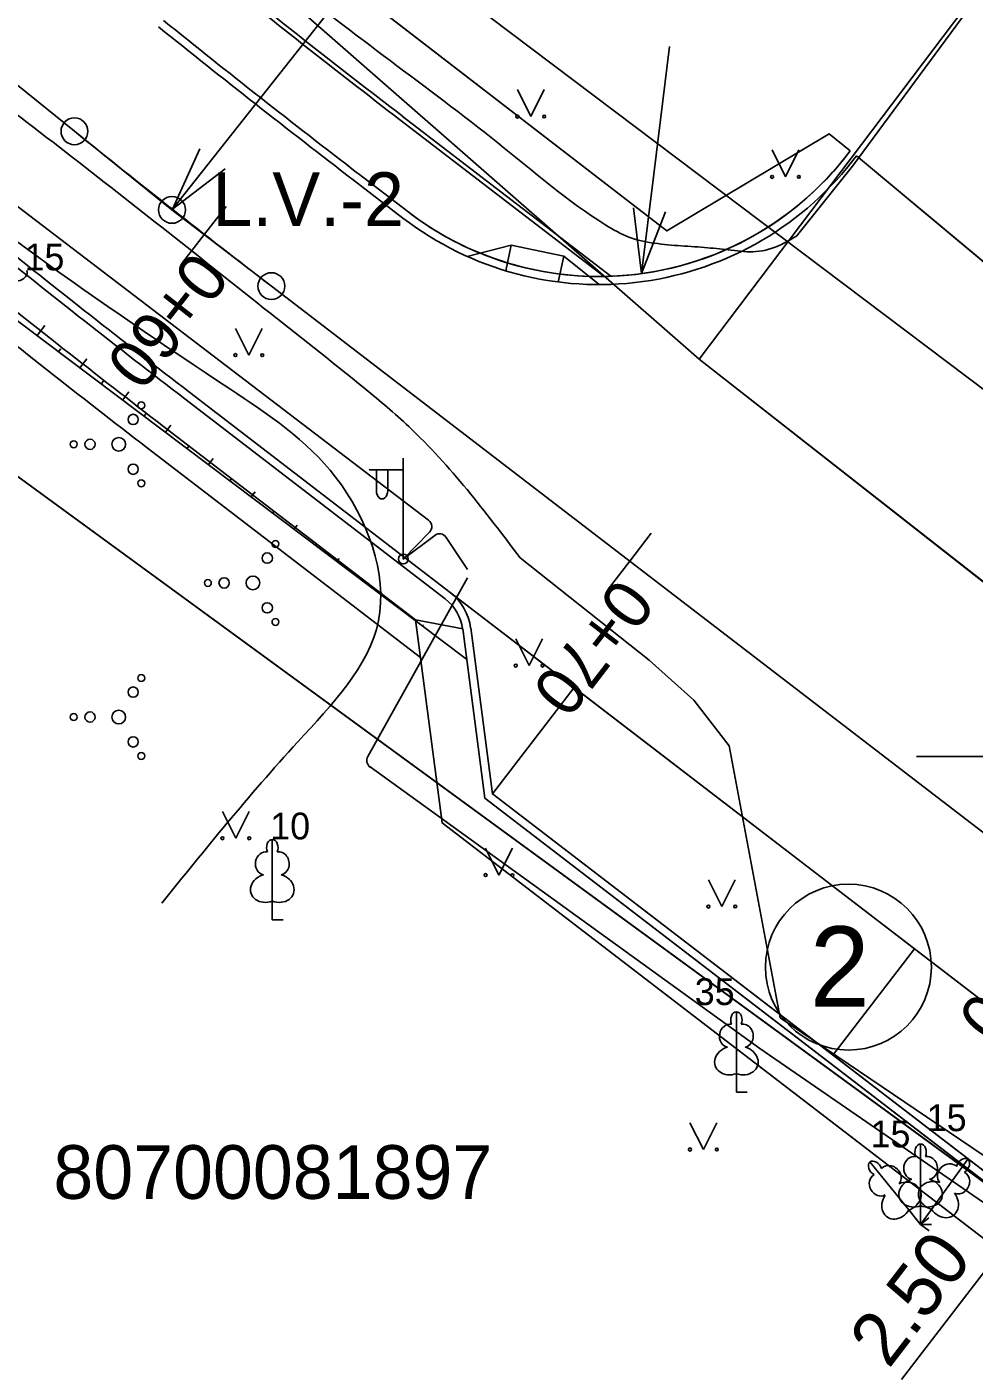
# Model space of a CAD drawing. Extents: x 514086 to 514457, y 297399 to 297567.
# Drawn here: x 514181.92 to 514199.57, y 297438.52 to 297463.61 of the extents above; entities that cross this region are included whole.
import ezdxf

# ---------------------------------------------------------------- set-up
doc = ezdxf.new("R2010")
doc.units = 0
for name, color, linetype in [('AA_Apzimejumi', 7, 'Continuous'), ('AA_Brauktuve', 7, 'Continuous'), ('AA_cela_mala', 7, 'Continuous'), ('AA_Ielas_ass', 7, 'Continuous'), ('AA_Ietve', 7, 'Continuous'), ('AA_izmeri', 7, 'Continuous'), ('AA_noejas', 7, 'Continuous'), ('AA_nogaze', 7, 'Continuous'), ('AA_Nomale', 7, 'Continuous'), ('AA_Stavvietas', 7, 'Continuous'), ('AA_Zale', 7, 'Continuous'), ('Level 1', 7, 'Continuous'), ('Level 21', 7, 'Continuous'), ('Level 23', 7, 'Continuous'), ('Level 29', 7, 'Continuous'), ('Level 30', 7, 'Continuous'), ('Level 37', 7, 'Continuous'), ('Level 44', 7, 'Continuous'), ('Level 45', 7, 'Continuous'), ('Level 46', 7, 'Continuous'), ('Level 59', 7, 'Continuous'), ('Level 8', 7, 'Continuous')]:
    doc.layers.add(name, color=color, linetype=linetype)

msp = doc.modelspace()

# ---------------------------------------------------------------- linework, layer by layer
at = {"layer": 'AA_Apzimejumi'}
msp.add_circle((514197.229, 297446.074), 1.546, dxfattribs=at)
at = {"layer": 'AA_Brauktuve'}
for points in [[(514201.37, 297457.873), (514197.38, 297461.203)], [(514188.925, 297460.043), (514187.996, 297460.756)], [(514184.951, 297456.79), (514189.806, 297453.062), (514189.806, 297453.062), (514192.117, 297451.287), (514198.462, 297446.415), (514204.811, 297441.539), (514204.858, 297441.502), (514204.858, 297441.502)], [(514204.858, 297441.502), (514204.858, 297441.502), (514204.811, 297441.539), (514198.462, 297446.415), (514192.117, 297451.287), (514189.806, 297453.062)], [(514190.188, 297452.399), (514190.594, 297449.304), (514203.335, 297439.52)]]:
    msp.add_lwpolyline(points, dxfattribs=at)
for centre, radius, start, end in [((514308.288, 297617.396), 197.5, 231.13942, 232.4775), ((514192.579, 297464.802), 6, 232.4775, 323.1507), ((514308.288, 297617.396), 202.5, 231.13942, 232.4775), ((514189.196, 297452.269), 1, 7.4775, 52.4769)]:
    msp.add_arc(centre, radius, start, end, dxfattribs=at)
at = {"layer": 'AA_cela_mala'}
for p, q in [((514192.676, 297458.952), (514188.861, 297461.882)), ((514188.91, 297461.945), (514192.803, 297458.956)), ((514197.38, 297461.203), (514201.37, 297457.873)), ((514189.016, 297460.162), (514188.088, 297460.875)), ((514187.996, 297460.756), (514188.925, 297460.043)), ((514184.951, 297456.79), (514189.806, 297453.062)), ((514184.86, 297456.671), (514189.714, 297452.943)), ((514189.806, 297453.062), (514204.858, 297441.502)), ((514190.039, 297452.38), (514190.454, 297449.223)), ((514190.594, 297449.304), (514190.188, 297452.399)), ((514190.594, 297449.304), (514203.335, 297439.52)), ((514190.454, 297449.223), (514203.244, 297439.401))]:
    msp.add_line(p, q, dxfattribs=at)
for centre, radius, start, end in [((514308.288, 297617.396), 196.08, 231.13942, 232.4775), ((514308.288, 297617.396), 196, 231.13942, 232.4775), ((514308.288, 297617.396), 197.5, 231.13942, 232.4775), ((514308.288, 297617.396), 197.35, 231.13942, 232.4775), ((514192.579, 297464.802), 5.85, 270.0269, 323.1507), ((514192.579, 297464.802), 6, 232.4775, 323.1507), ((514192.579, 297464.802), 5.85, 232.4775, 245.8215), ((514308.288, 297617.396), 202.65, 231.13942, 232.4775), ((514308.288, 297617.396), 202.5, 231.13942, 232.4775), ((514192.579, 297464.802), 5.85, 245.8215, 270.0269), ((514189.196, 297452.269), 1, 7.4775, 52.4775), ((514189.196, 297452.269), 0.85, 7.4766, 52.4772)]:
    msp.add_arc(centre, radius, start, end, dxfattribs=at)
at = {"layer": 'AA_Ielas_ass'}
for p, q in [((514159.568, 297480.383), (514182.803, 297461.661)), ((514182.803, 297461.661), (514184.621, 297460.195)), ((514184.621, 297460.195), (514186.474, 297458.773)), ((514185.226, 297459.74), (514185.63, 297460.259)), ((514185.226, 297459.74), (514184.821, 297459.222)), ((514186.474, 297458.773), (514206.381, 297443.485)), ((514193.152, 297453.644), (514193.553, 297454.166)), ((514193.152, 297453.644), (514192.752, 297453.122))]:
    msp.add_line(p, q, dxfattribs=at)
for centre in [(514182.803, 297461.661), (514184.621, 297460.195), (514186.474, 297458.773)]:
    msp.add_circle(centre, 0.25, dxfattribs=at)
msp.add_arc((514308.288, 297617.396), 200, 231.13942, 232.4775, dxfattribs=at)
at = {"layer": 'AA_Ietve'}
for points in [[(514192.676, 297458.952), (514188.861, 297461.882)], [(514188.088, 297460.875), (514189.016, 297460.162)]]:
    msp.add_lwpolyline(points, dxfattribs=at)
for centre, radius, start, end in [((514308.288, 297617.396), 196.08, 231.13942, 232.4775), ((514308.288, 297617.396), 197.35, 231.13942, 232.4775), ((514192.579, 297464.802), 5.85, 232.4775, 270.9501)]:
    msp.add_arc(centre, radius, start, end, dxfattribs=at)
at = {"layer": 'AA_izmeri'}
for p, q in [((514184.63, 297460.206), (514187.714, 297464.105)), ((514193.894, 297463.24), (514193.602, 297460.858)), ((514193.374, 297459.006), (514193.602, 297460.858)), ((514198.217, 297438.384), (514200.665, 297441.571))]:
    msp.add_line(p, q, dxfattribs=at)
for points in [[(514185.61, 297460.961), (514184.63, 297460.206), (514185.139, 297461.333)], [(514193.818, 297460.16), (514193.374, 297459.006), (514193.223, 297460.233)]]:
    msp.add_lwpolyline(points, dxfattribs=at)
at = {"layer": 'AA_noejas'}
for p, q in [((514190.944, 297459.54), (514190.122, 297459.328)), ((514190.841, 297459.059), (514190.944, 297459.54)), ((514190.944, 297459.54), (514191.922, 297459.33)), ((514191.819, 297458.85), (514191.922, 297459.33)), ((514191.922, 297459.33), (514192.582, 297458.802))]:
    msp.add_line(p, q, dxfattribs=at)
at = {"layer": 'AA_nogaze'}
for p, q in [((514182.107, 297457.854), (514182.248, 297458.041)), ((514182.506, 297457.553), (514182.546, 297457.606)), ((514182.905, 297457.252), (514183.032, 297457.42)), ((514183.304, 297456.951), (514183.34, 297456.999)), ((514183.704, 297456.65), (514183.817, 297456.8)), ((514184.103, 297456.349), (514184.135, 297456.391)), ((514184.502, 297456.048), (514184.601, 297456.179)), ((514184.901, 297455.747), (514184.929, 297455.783)), ((514185.301, 297455.446), (514185.386, 297455.558)), ((514185.7, 297455.145), (514185.723, 297455.176)), ((514186.099, 297454.844), (514186.17, 297454.938)), ((514186.498, 297454.543), (514186.517, 297454.568)), ((514186.898, 297454.242), (514186.954, 297454.317)), ((514187.297, 297453.941), (514187.312, 297453.96)), ((514187.696, 297453.64), (514187.739, 297453.696)), ((514188.095, 297453.339), (514188.106, 297453.353)), ((514188.495, 297453.038), (514188.523, 297453.075)), ((514188.894, 297452.737), (514188.9, 297452.745)), ((514189.293, 297452.436), (514189.307, 297452.455)), ((514189.692, 297452.135), (514189.694, 297452.137)), ((514190.092, 297451.834), (514190.092, 297451.834))]:
    msp.add_line(p, q, dxfattribs=at)
msp.add_lwpolyline([(514139.381, 297492.411), (514153.448, 297479.653), (514157.356, 297476.515), (514190.113, 297451.817)], dxfattribs=at)
at = {"layer": 'AA_Nomale'}
for points in [[(514189.714, 297452.943), (514184.86, 297456.671)], [(514184.464, 297456.156), (514189.16, 297452.549), (514190.039, 297452.38)]]:
    msp.add_lwpolyline(points, dxfattribs=at)
for centre, radius, start, end in [((514308.288, 297617.396), 202.65, 231.13942, 232.4775), ((514308.288, 297617.396), 203.3, 231.13942, 232.4775), ((514189.196, 297452.269), 0.85, 7.4766, 52.4772)]:
    msp.add_arc(centre, radius, start, end, dxfattribs=at)
at = {"layer": 'AA_Stavvietas'}
for p, q in [((514190.594, 297449.304), (514192.117, 297451.287)), ((514196.939, 297444.432), (514198.462, 297446.415))]:
    msp.add_line(p, q, dxfattribs=at)
at = {"layer": 'AA_Zale'}
for p, q in [((514175.859, 297473.677), (514193.845, 297459.804)), ((514196.873, 297461.611), (514193.845, 297459.804)), ((514197.26, 297461.293), (514196.873, 297461.611)), ((514184.464, 297456.156), (514189.16, 297452.549)), ((514184.159, 297455.759), (514189.252, 297451.848)), ((514189.657, 297448.764), (514189.16, 297452.549)), ((514189.16, 297452.549), (514190.039, 297452.38)), ((514189.657, 297448.764), (514202.726, 297438.727))]:
    msp.add_line(p, q, dxfattribs=at)
for points in [[(514197.26, 297461.293), (514196.873, 297461.611), (514193.845, 297459.804), (514175.859, 297473.677), (514146.591, 297497.26)], [(514188.91, 297461.945), (514192.803, 297458.956)], [(514184.159, 297455.759), (514189.252, 297451.848), (514189.16, 297452.549), (514184.464, 297456.156)], [(514203.244, 297439.401), (514190.454, 297449.223), (514190.039, 297452.38), (514189.16, 297452.549), (514189.657, 297448.764), (514202.726, 297438.727)]]:
    msp.add_lwpolyline(points, dxfattribs=at)
for centre, radius, start, end in [((514308.288, 297617.396), 196, 231.13942, 232.4775), ((514192.579, 297464.802), 5.85, 272.1926, 323.1507), ((514308.288, 297617.396), 203.3, 231.13942, 232.4775), ((514308.288, 297617.396), 203.3, 231.13942, 232.4775), ((514308.288, 297617.396), 203.8, 231.13942, 232.4775), ((514308.288, 297617.396), 203.8, 231.13942, 232.4775)]:
    msp.add_arc(centre, radius, start, end, dxfattribs=at)
at = {"layer": 'Level 1'}
for p, q in [((514186.491, 297447.302), (514186.491, 297446.955)), ((514186.491, 297446.955), (514186.691, 297446.955)), ((514195.14, 297444.087), (514195.14, 297443.74)), ((514195.14, 297443.74), (514195.34, 297443.74)), ((514198.356, 297441.545), (514198.575, 297441.275)), ((514198.575, 297441.622), (514198.575, 297441.275)), ((514198.778, 297441.556), (514198.575, 297441.275)), ((514198.575, 297441.275), (514198.73, 297441.401)), ((514198.575, 297441.275), (514198.775, 297441.275)), ((514198.575, 297441.275), (514198.737, 297441.158))]:
    msp.add_line(p, q, dxfattribs=at)
for points in [[(514186.491, 297448.455), (514186.491, 297447.302)], [(514186.581, 297448.223), (514186.58, 297448.224)], [(514195.14, 297445.24), (514195.14, 297444.087)], [(514195.23, 297445.008), (514195.229, 297445.009)], [(514198.575, 297442.775), (514198.575, 297441.622)], [(514198.665, 297442.543), (514198.664, 297442.544)], [(514199.454, 297442.491), (514198.778, 297441.556)], [(514197.63, 297442.44), (514198.356, 297441.545)], [(514197.846, 297442.316), (514197.844, 297442.316)], [(514199.39, 297442.25), (514199.39, 297442.251)]]:
    msp.add_lwpolyline(points, dxfattribs=at)
for centre, major_axis, ratio, start_param, end_param in [((514181.781, 297458.991), (-0.13, -0.075), 0.707107, 0.995701, 3.137816), ((514186.363, 297448.01), (-0.039, -0.212), 0.861323, 3.141593, 6.283185), ((514186.491, 297448.305), (0, -0.15), 0.707107, 3.14537, 5.287485), ((514186.491, 297448.305), (0, -0.15), 0.707107, 0.995701, 3.137816), ((514186.619, 297448.01), (0.039, -0.212), 0.861323, 0, 3.141593), ((514186.401, 297447.548), (0.307, 0.095), 0.814445, 1.570796, 4.752015), ((514186.581, 297447.548), (-0.307, 0.095), 0.814445, 1.531171, 4.712389), ((514195.141, 297445.09), (0, -0.15), 0.707107, 3.14537, 5.287485), ((514195.14, 297445.09), (0, -0.15), 0.707107, 0.995701, 3.137816), ((514195.012, 297444.796), (-0.039, -0.212), 0.861323, 3.141593, 6.283185), ((514195.269, 297444.796), (0.039, -0.212), 0.861323, 0, 3.141593), ((514195.051, 297444.333), (0.307, 0.095), 0.814445, 1.570796, 4.752015), ((514195.23, 297444.333), (-0.307, 0.095), 0.814445, 1.531171, 4.712389), ((514198.575, 297442.625), (0, -0.15), 0.707107, 3.14537, 5.287485), ((514198.575, 297442.625), (0, -0.15), 0.707107, 0.995701, 3.137816), ((514197.724, 297442.323), (0.094, -0.116), 0.707107, 0.995701, 3.137816), ((514198.447, 297442.33), (-0.039, -0.212), 0.861323, 3.141593, 6.283185), ((514198.703, 297442.33), (0.039, -0.212), 0.861323, 0, 3.141593), ((514199.366, 297442.369), (-0.088, -0.122), 0.707107, 3.14537, 5.287485), ((514199.365, 297442.37), (-0.088, -0.122), 0.707107, 0.995701, 3.137816), ((514197.725, 297442.324), (0.094, -0.116), 0.707107, 3.14537, 5.287485), ((514198.01, 297442.175), (0.164, -0.141), 0.861323, 0, 3.141593), ((514199.089, 297442.206), (-0.156, -0.149), 0.861323, 3.141593, 6.283185), ((514199.297, 297442.055), (-0.093, -0.195), 0.861323, 0, 3.141593), ((514197.81, 297442.014), (0.104, -0.189), 0.861323, 3.141593, 6.283185), ((514198.485, 297441.868), (0.307, 0.095), 0.814445, 1.570796, 4.752015), ((514198.271, 297441.792), (-0.298, -0.119), 0.814445, 1.531171, 4.712389), ((514198.85, 297441.808), (0.304, -0.103), 0.814445, 1.570796, 4.752015), ((514198.665, 297441.868), (-0.307, 0.095), 0.814445, 1.531171, 4.712389), ((514198.132, 297441.679), (0.178, 0.267), 0.814445, 1.570796, 4.752015), ((514198.995, 297441.703), (-0.193, 0.257), 0.814445, 1.531171, 4.712389)]:
    msp.add_ellipse(centre, major_axis=major_axis, ratio=ratio, start_param=start_param, end_param=end_param, dxfattribs=at)
at = {"layer": 'Level 21'}
msp.add_spline([(514167.656, 297460.196), (514167.656, 297463.017), (514169.677, 297465.792), (514173.482, 297465.792), (514178.65, 297462.077), (514185.698, 297456.857), (514187.671, 297455.211), (514188.469, 297452.531), (514186.966, 297450.274), (514184.429, 297447.265)], degree=3, dxfattribs=at)
at = {"layer": 'Level 23'}
for p, q in [((514191.058, 297462.437), (514191.308, 297461.937)), ((514191.308, 297461.937), (514191.558, 297462.437)), ((514195.806, 297461.312), (514196.056, 297460.812)), ((514196.056, 297460.812), (514196.306, 297461.312)), ((514185.804, 297457.986), (514186.054, 297457.486)), ((514186.054, 297457.486), (514186.304, 297457.986)), ((514191.028, 297452.197), (514191.278, 297451.697)), ((514191.278, 297451.697), (514191.528, 297452.197)), ((514185.562, 297448.978), (514185.812, 297448.478)), ((514185.812, 297448.478), (514186.062, 297448.978)), ((514190.466, 297448.29), (514190.716, 297447.79)), ((514190.716, 297447.79), (514190.966, 297448.29)), ((514194.62, 297447.704), (514194.87, 297447.204)), ((514194.87, 297447.204), (514195.12, 297447.704)), ((514194.276, 297443.173), (514194.526, 297442.673)), ((514194.526, 297442.673), (514194.776, 297443.173))]:
    msp.add_line(p, q, dxfattribs=at)
for centre, radius in [((514191.058, 297461.936), 0.028), ((514191.558, 297461.936), 0.0263), ((514195.806, 297460.811), 0.028), ((514196.306, 297460.811), 0.0263), ((514185.804, 297457.486), 0.028), ((514186.304, 297457.486), 0.0263), ((514184.049, 297456.55), 0.064), ((514183.897, 297456.287), 0.096), ((514182.79, 297455.823), 0.064), ((514183.093, 297455.823), 0.096), ((514183.629, 297455.823), 0.128), ((514183.897, 297455.359), 0.096), ((514184.049, 297455.096), 0.064), ((514186.549, 297453.965), 0.064), ((514186.397, 297453.702), 0.096), ((514185.29, 297453.238), 0.064), ((514185.593, 297453.238), 0.096), ((514186.129, 297453.238), 0.128), ((514186.397, 297452.774), 0.096), ((514186.549, 297452.511), 0.064), ((514184.049, 297451.465), 0.064), ((514191.028, 297451.696), 0.028), ((514191.528, 297451.696), 0.0263), ((514183.897, 297451.202), 0.096), ((514182.79, 297450.738), 0.064), ((514183.093, 297450.738), 0.096), ((514183.629, 297450.738), 0.128), ((514183.897, 297450.274), 0.096), ((514184.049, 297450.011), 0.064), ((514185.562, 297448.477), 0.028), ((514186.062, 297448.477), 0.0263), ((514190.466, 297447.79), 0.028), ((514190.966, 297447.79), 0.0263), ((514194.62, 297447.204), 0.028), ((514195.12, 297447.204), 0.0263), ((514194.276, 297442.673), 0.028), ((514194.776, 297442.673), 0.0263)]:
    msp.add_circle(centre, radius, dxfattribs=at)
at = {"layer": 'Level 29'}
for p, q in [((514139.134, 297486.37), (514229.261, 297420.493)), ((514194.45, 297457.413), (514203.568, 297469.479)), ((514209.969, 297445.237), (514194.45, 297457.413))]:
    msp.add_line(p, q, dxfattribs=at)
at = {"layer": 'Level 30'}
msp.add_line((514198.5, 297450), (514200, 297450), dxfattribs=at)
at = {"layer": 'Level 37'}
for points in [[(514201.367, 297466.523), (514197.303, 297461.007), (514196.259, 297459.707)], [(514210.686, 297435.157), (514195.954, 297445.131), (514195.007, 297450.2), (514194.35, 297451.053), (514193.518, 297451.797), (514191.11, 297453.709)]]:
    msp.add_lwpolyline(points, dxfattribs=at)
for points in [[(514139.874, 297497.035), (514148.452, 297493.087), (514152.9, 297490.654), (514155.012, 297489.24), (514157.055, 297487.727), (514160.163, 297485.252), (514163.225, 297482.729), (514166.288, 297480.21), (514169.399, 297477.75), (514184.679, 297466.049), (514188.685, 297462.979), (514190.692, 297461.445), (514192.708, 297459.912), (514193.134, 297459.688), (514193.613, 297459.574), (514194.114, 297459.524), (514194.606, 297459.489), (514195.045, 297459.442), (514195.506, 297459.417), (514195.979, 297459.548), (514196.259, 297459.707)], [(514136.849, 297494.086), (514140.775, 297492.444), (514142.699, 297491.153), (514143.967, 297490.173), (514145.225, 297489.179), (514146.485, 297488.19), (514147.764, 297487.226), (514149.635, 297485.885), (514151.52, 297484.563), (514153.402, 297483.236), (514155.263, 297481.88), (514159.161, 297478.934), (514163.043, 297475.965), (514166.923, 297472.996), (514170.82, 297470.048), (514173.26, 297468.237), (514175.709, 297466.438), (514178.159, 297464.639), (514180.6, 297462.828), (514184.429, 297459.874), (514186.323, 297458.371), (514188.215, 297456.863), (514189.034, 297456.154), (514191.11, 297453.709)]]:
    msp.add_spline(points, degree=3, dxfattribs=at)
at = {"layer": 'Level 44'}
for p, q in [((514188.932, 297453.684), (514188.932, 297455.567)), ((514188.932, 297455.347), (514188.297, 297455.347)), ((514188.432, 297455.347), (514188.432, 297454.955)), ((514188.642, 297455.347), (514188.642, 297454.955))]:
    msp.add_line(p, q, dxfattribs=at)
msp.add_circle((514188.932, 297453.684), 0.09, dxfattribs=at)
msp.add_ellipse((514188.537, 297454.955), major_axis=(0, 0.151), ratio=0.695971, start_param=1.570796, end_param=4.712389, dxfattribs=at)
at = {"layer": 'Level 45'}
for points in [[(514165.491, 297472.425), (514167.329, 297470.46), (514170.146, 297468.31), (514175.888, 297464.328), (514181.629, 297460.345), (514185.517, 297457.375), (514189.404, 297454.406)], [(514189.42, 297454.182), (514188.932, 297453.684), (514189.518, 297454.125)], [(514189.734, 297454.088), (514190.126, 297453.486)], [(514190.131, 297453.331), (514188.27, 297450.001)], [(514188.313, 297449.806), (514195.576, 297444.559), (514209.025, 297435.296), (514213.532, 297432.769)]]:
    msp.add_lwpolyline(points, dxfattribs=at)
for centre, start, end in [((514189.313, 297454.287), 315.5749, 52.6281), ((514189.608, 297454.006), 33.0661, 126.9951), ((514188.401, 297449.927), 150.8076, 234.1547)]:
    msp.add_arc(centre, 0.15, start, end, dxfattribs=at)
at = {"layer": 'Level 46'}
msp.add_lwpolyline([(514139.134, 297486.37), (514229.261, 297420.493), (514237.863, 297414.208), (514250.009, 297428.181), (514295.433, 297494.723), (514312.775, 297524.542), (514316.491, 297528.738), (514320.446, 297531.016), (514328.236, 297532.215), (514332.539, 297530.572), (514332.631, 297530.536), (514341.642, 297542.18), (514320.211, 297553.997), (514285.885, 297496.27), (514243.195, 297433.696), (514241.534, 297432.407), (514239.451, 297432.203), (514209.969, 297445.237), (514194.45, 297457.413), (514175.859, 297473.677), (514139.316, 297503.122), (514133.046, 297508.174), (514130.604, 297489.221)], close=True, dxfattribs=at)
at = {"layer": 'Level 8'}
msp.add_lwpolyline([(514200.623, 297456.189), (514178.139, 297473.151), (514155.647, 297490.079), (514143.111, 297496.557), (514135.656, 297500), (514119.377, 297505.512), (514108.036, 297513.213), (514096.037, 297522.278)], dxfattribs=at)

# ---------------------------------------------------------------- texts
at = {"layer": 'AA_Apzimejumi'}
msp.add_text('2', height=1.5, dxfattribs=at).set_placement((514196.509, 297445.334))
at = {"layer": 'AA_Ielas_ass'}
for s, height, rotation, p in [('L.V.-2', 1, 360, (514185.376, 297459.894)), (' 0+60', 0.9, 232.0453, (514185.226, 297459.74)), (' 0+70', 0.9, 232.4775, (514193.152, 297453.644)), (' 0+80', 0.9, 232.4775, (514201.084, 297447.553))]:
    msp.add_text(s, height=height, rotation=rotation, dxfattribs=at).set_placement(p)
at = {"layer": 'AA_izmeri'}
msp.add_text('2.50', height=1, rotation=52.4728, dxfattribs=at).set_placement((514197.979, 297438.567))
at = {"layer": 'Level 1'}
for s, p in [(' 15', (514181.686, 297459.066)), (' 10', (514186.266, 297448.455)), ('35', (514194.365, 297445.367)), ('15', (514198.688, 297443.015)), ('15', (514197.641, 297442.713))]:
    msp.add_text(s, height=0.5, dxfattribs=at).set_placement(p)
at = {"layer": 'Level 59'}
msp.add_text('80700081897', height=1, dxfattribs=at).set_placement((514182.41, 297441.753))

doc.saveas('drawing.dxf')
